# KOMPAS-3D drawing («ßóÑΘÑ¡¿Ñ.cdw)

Referenced files in D:\1я детская\: освещение.cdw
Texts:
  Реконструкция элеткроснабжения помещений 2 го этажа  первой детской городской больницы
  Microsoft
  Текст на чертеже
  Размерные надписи
  Шероховатость
  Линия-выноска #1
  Линия-выноска #2
  Линия-выноска #3
  Отклонения формы и база
  Заголовок таблицы
  Ячейка таблицы
  Стрелка вида
  Обозначение изменения
  Фигурная скобка
  Номер узла
  Марка координационной оси
  VRCB
  Выносная надпись
  Обозначение узла
  Марка/позиционное обозначение с линией-выноской
  Марка/позиционное обозначение на линии
  Марка/позиционное обозначение без линии-выноски
  Слой 1
  "не входить"
  НСП 1х60 Вт
  темп. реле
  РЩ1
  РЩ2
  РЩ3
  гр.1
  гр.2
  гр.3
  гр.4
  гр.10
  гр.11
  гр.12
  гр.13
  гр.5
  гр.6
  гр.14
  гр.15
  "Выход"
  РЩ4
  ЩАО
  гр.16
  гр.17
  гр.18
  гр.19
  гр. 20
  гр. 21
  гр. 22
  гр. 23
  гр.31
  гр.32
  гр.33
  гр.34
  гр.35
  гр.36
  гр.37
  гр.38
  гр.39
  гр.42
  гр.43
  гр.44
  гр.45
  гр.48
  гр.49
  гр.50
  гр.46
  гр.47
  РЩ5
  РЩ6
  РЩ7
  Реконструкция элеткроснабжения помещений 2 го этажа
  первой детской городской больницы
  ГИП
  План сети освещения 2 го этажа
Dimensions and other numbers on the sheet: 7; 3НСП 1х60 Вт; 2ARS/R 4[18 Вт; 2НСП 1х60 Вт; 7ARS/R 4х18 Вт; 3ЛСП 1х60 Вт IP54; 4ARS/R 4х18 Вт; 3ARS/R 4х18 Вт; 6ЛСП 2х36 Вт; 1:1; 5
